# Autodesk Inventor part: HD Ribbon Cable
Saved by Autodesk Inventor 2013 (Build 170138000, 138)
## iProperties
Created: 2007-02
Part Number: HD Ribbon Cable
Document SubType Name: Modeling
Designer: floress
Density: 1 g/cm^3
Material: Allgemein
Author: floress
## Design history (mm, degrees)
workpoint "Work Point1"
workpoint "Work Point2"
sketch "RibbonCable1"
workpoint "Work Point3"
workpoint "Work Point4"
workpoint "Work Point5"
workpoint "Work Point6"
workpoint "Work Point7"
workpoint "Work Point8"
workpoint "Work Point9"
workpoint "Work Point10"
workpoint "Work Point11"
workpoint "Work Point12"
workpoint "Work Point15"
workpoint "Work Point16"
workpoint "Work Point17"
workpoint "Work Point18"
workpoint "Work Point19"
sketch "Sketch75"
  geometry: C1 r 0.445 at (0, -24.765)
  constraints: 1 centre point
sketch "Sketch76"
  geometry: C1 r 0.445 at (0, 24.765)
  constraints: 1 centre point
sketch "Sketch77"
  geometry: L1 (0, -25.4)-(0, 25.4)
  constraints: 2 end point
feature "SweepSrf45" dims "d44" = 0
feature "SweepSrf46" dims "d45" = 0
feature "SweepSrf47" dims "d46" = 0
sketch "Sketch78"
  geometry: C1 r 0.445 at (0, -24.765)
  constraints: 1 centre point
sketch "Sketch79"
  geometry: C1 r 0.445 at (0, 24.765)
  constraints: 1 centre point
sketch "Sketch80"
  geometry: L1 (0, -25.4)-(0, 25.4)
  constraints: 2 end point
feature "SweepSrf48" dims "d47" = 0
feature "SweepSrf49" dims "d48" = 0
feature "SweepSrf50" dims "d49" = 0
sketch "Sketch81"
  geometry: L1 (25.4, 25.4)-(25.4, -25.4); L2 (25.4, -25.4)-(-25.4, -25.4); L3 (-25.4, -25.4)-(25.4, 25.4)
  constraints: 6 end point
patch "Boundary Patch3" sketch "Sketch81"
sketch "Sketch82"
  geometry: L1 (25.4, 25.4)-(25.4, -25.4); L2 (25.4, -25.4)-(-25.4, -25.4); L3 (-25.4, -25.4)-(-25.4, 25.4); L4 (-25.4, 25.4)-(25.4, 25.4)
  constraints: 8 end point
patch "Boundary Patch4" sketch "Sketch82"
sketch "3D Sketch17"
sketch "Sketch83"
  geometry: C1 r 0.445 at (0, 0)
  constraints: 1 centre point
feature "SweepSrf51" sketch "3D Sketch17", "Sketch83" dims "d50" = 0
sketch "3D Sketch18"
sketch "Sketch84"
  geometry: C1 r 0.445 at (0, 0)
  constraints: 1 centre point
feature "SweepSrf52" sketch "3D Sketch18", "Sketch84" dims "d51" = 0
sketch "3D Sketch19"
sketch "Sketch85"
  geometry: C1 r 0.445 at (0, 0)
  constraints: 1 centre point
feature "SweepSrf53" sketch "3D Sketch19", "Sketch85" dims "d52" = 0
body "Srf1"
body "Srf2"
body "Srf3"
body "Srf4"
body "Srf5"
body "Srf6"
body "Srf7"
body "Srf8"
body "Srf9"
body "Srf10"
body "Srf11"
